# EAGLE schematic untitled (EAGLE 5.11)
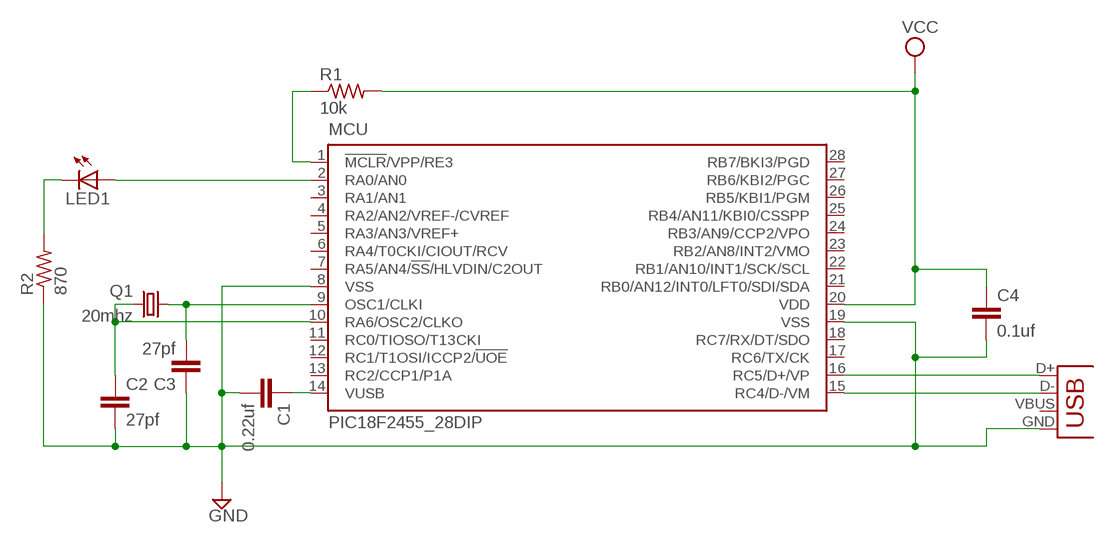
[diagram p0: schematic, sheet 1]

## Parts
C1  0.22uf  C-EU025-030X050  [C025-030X050]
C2  27pf  C-EU025-030X050  [C025-030X050]
C3  27pf  C-EU025-030X050  [C025-030X050]
C4  0.1uf  C-EU025-030X050  [C025-030X050]
LED1  LED5MM  [LED5MM]
MCU  PIC18F2455_28DIP  [DIL28-3]
Q1  20mhz  CRYSTALHC49S  [HC49/S]
R1  10k  R-US_0207/7  [0207/7]
R2  870  R-US_0207/7  [0207/7]
X1  USBPTH  [USB-B-PTH]

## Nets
GND: C1.2 C2.2 C3.1 C4.2 MCU.8(VSS) MCU.19(VSS) R2.1 X1.GND
N$1: C1.1 MCU.14(VUSB)
N$2: C2.1 MCU.10(RA6/OSC2/CLKO) Q1.2
N$3: C3.2 MCU.9(OSC1/CLKI) Q1.1
N$5: LED1.A MCU.2(RA0/AN0)
N$6: MCU.1(!MCLR!/VPP/RE3) R1.1
N$8: LED1.K(C) R2.2
N$9: MCU.16(RC5/D+/VP) X1.D+
N$11: MCU.15(RC4/D-/VM) X1.D-
VCC: C4.1 MCU.20(VDD) R1.2
Unconnected: MCU.3(RA1/AN1) MCU.4(RA2/AN2/VREF-/CVREF) MCU.5(RA3/AN3/VREF+) MCU.6(RA4/T0CKI/CIOUT/RCV) MCU.7(RA5/AN4/!SS!/HLVDIN/C2OUT) MCU.11(RC0/TIOSO/T13CKI) MCU.12(RC1/T1OSI/ICCP2/!UOE) MCU.13(RC2/CCP1/P1A) MCU.17(RC6/TX/CK) MCU.18(RC7/RX/DT/SDO) MCU.21(RB0/AN12/INT0/LFT0/SDI/SDA) MCU.22(RB1/AN10/INT1/SCK/SCL) MCU.23(RB2/AN8/INT2/VMO) MCU.24(RB3/AN9/CCP2/VPO) MCU.25(RB4/AN11/KBI0/CSSPP) MCU.26(RB5/KBI1/PGM) MCU.27(RB6/KBI2/PGC) MCU.28(RB7/BKI3/PGD) X1.VBUS

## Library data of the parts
C1-C4 = rcl:C-EU: CAPACITOR, European symbol
LED1 = led:LED: LED
MCU = microchip:PIC18F2*_28: USB Microcontrollers with nanoWatt Technology High-Performance, Enhanced Flash, 28/40/44-Pin, Source: http://ww1.microchip.com/downloads/en/devicedoc/39632c.pdf; MF: MICROCHIP; MPN: PIC18F2455-I/SP; OC_FARNELL: 1579600; OC_NEWARK: 01M8485
Q1 = crystal:CRYSTAL: CRYSTAL; OC_FARNELL: 1667008; OC_NEWARK: unknown
R1 R2 = resistor:R-US_: RESISTOR, American symbol
X1 = SparkFun2011-02-20:USB: USB Connectors USB-B-PTH is fully proven SKU : PRT-00139 USB-miniB is fully proven SKU : PRT-00587 USB-A-PCB is untested. USB-A-H is throughly reviewed, but untested. Spark Fun Electronics SKU : PRT-00437 USB-B-SMT is throughly reviewed, but untested. Needs silkscreen touching up. USB-A-S has not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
